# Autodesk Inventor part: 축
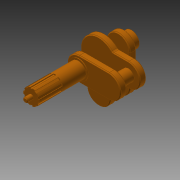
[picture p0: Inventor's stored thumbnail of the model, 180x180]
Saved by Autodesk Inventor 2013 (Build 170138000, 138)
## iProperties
Created: 2017-05
Part Number: 축
Material: 강철, 연강
Document SubType Name: Modeling
Designer: mduedu
Density: 7.86 g/cm^3
Mass: 656.198 g
Surface Area: 242.498 cm^2
Volume: 83.4857 cm^3
Author: mduedu
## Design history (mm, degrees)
sketch "스케치1"
  geometry: L1 (-38, 15)-(-17.436, 15); L2 (-38, -15)-(-17.436, -15); L3 (-15, -38)-(-15, -17.436); L4 (15, -38)-(15, -17.436); A1 r 23 centre (0, 0) between (-17.436, 15) and (-17.436, -15); A2 r 15 centre (-38, 0) between (-38, 15) and (-38, -15); A3 r 15 centre (0, -38) between (-15, -38) and (15, -38); 1 further point
  constraints: 8 end point, 8 point on circle, 4 tangent, 3 centre point, 2 horizontal, 2 vertical, 1 coincident, 1 horizontal alignment, 1 vertical alignment
  dimensions: "d0" = 46 diameter of A1; "d1" = 30 diameter of A2; "d2" = 30 diameter of A3 (= d1); "d3" = 38 distance of point (0, 0) A2.centre; "d4" = 38 distance of A3.centre point (0, 0)
extrude "돌출1" new body sketch "스케치1" distance "d5" = 8; taper "d6" = 0 deg
fillet "모깎기1" dims "d7" = 3
sketch "스케치2"
  geometry: C1 r 7.5 at (0, -38); A1 r 15 centre (0, -38) between (-15, -38) and (15, -38) reference; 1 further point
  constraints: 1 centre point, 1 coincident
  dimensions: "d8" = 15 diameter of C1
extrude "돌출2" join sketch "스케치2" distance "d9" = 17; taper "d10" = 0 deg
sketch "스케치3"
  geometry: L1 (-15, 0)-(-15, 38); L2 (15, 0)-(15, 38); C1 r 7.5 at (0, 0) reference; A1 r 15 centre (0, 0) between (-15, 0) and (15, 0); A2 r 15 centre (0, 38) between (-15, 38) and (15, 38); 1 further point
  constraints: 4 end point, 4 point on circle, 4 tangent, 2 centre point, 2 coincident
  dimensions: "d11" = 30 diameter of A1; "d12" = 30 diameter of A2 (= d11)
extrude "돌출3" join sketch "스케치3" distance "d13" = 8; taper "d14" = 0 deg
sketch "스케치4"
  geometry: C1 r 12 at (0, 38); A1 r 15 centre (0, 38) between (15, 38) and (-15, 38) reference; 1 further point
  constraints: 1 centre point, 1 coincident
  dimensions: "d15" = 24 diameter of C1
extrude "돌출4" join sketch "스케치4" distance "d16" = 1; taper "d17" = 0 deg
sketch "스케치5"
  geometry: C1 r 10 at (0, 0); 1 further point
  constraints: 1 centre point, 1 coincident
  dimensions: "d18" = 20 diameter of C1
extrude "돌출5" join sketch "스케치5" distance "d19" = 8; taper "d20" = 0 deg
sketch "스케치6"
  geometry: C1 r 7.5 at (38, 0); A1 r 15 centre (38, 0) between (38, -15) and (38, 15) reference; 1 further point
  constraints: 1 centre point, 1 coincident
  dimensions: "d21" = 15 diameter of C1
extrude "돌출6" join sketch "스케치6" distance "d22" = 17; taper "d23" = 0 deg
sketch "스케치7"
  geometry: L1 (-38, 15)-(0, 15); L2 (-38, -15)-(0, -15); C1 r 7.5 at (0, 0) reference; A1 r 15 centre (0, 0) between (0, 15) and (0, -15); A2 r 15 centre (-38, 0) between (-38, 15) and (-38, -15); 1 further point
  constraints: 4 end point, 4 point on circle, 4 tangent, 2 centre point, 2 coincident
  dimensions: "d24" = 30 diameter of A1; "d25" = 30 diameter of A2 (= d24)
extrude "돌출7" join sketch "스케치7" distance "d26" = 8; taper "d27" = 0 deg
sketch "스케치8"
  geometry: C1 r 12 at (-38, 0); 1 further point
  constraints: 1 centre point, 1 coincident
  dimensions: "d28" = 24 diameter of C1
extrude "돌출8" join sketch "스케치8" distance "d29" = 1; taper "d30" = 0 deg
sketch "스케치9"
  geometry: C1 r 10 at (0, 0); 1 further point
  constraints: 1 centre point, 1 coincident
  dimensions: "d31" = 20 diameter of C1
extrude "돌출9" join sketch "스케치9" distance "d32" = 30; taper "d33" = 0 deg
sketch "스케치10"
  geometry: L1 (1.5, 9.887)-(1.5, 8.887); L2 (1.5, 8.887)-(-1.5, 8.887); L3 (-1.5, 8.887)-(-1.5, 9.887); L4 (-4.598, 8.88)-(-4.01, 8.071); L5 (-4.01, 8.071)-(-6.437, 6.308); L6 (-6.437, 6.308)-(-7.025, 7.117); L7 (-8.939, 4.482)-(-7.988, 4.173); L8 (-7.988, 4.173)-(-8.915, 1.32); L9 (-8.915, 1.32)-(-9.866, 1.629); L10 (-9.866, -1.629)-(-8.915, -1.32); L11 (-8.915, -1.32)-(-7.988, -4.173); L12 (-7.988, -4.173)-(-8.939, -4.482); L13 (-7.025, -7.117)-(-6.437, -6.308); L14 (-6.437, -6.308)-(-4.01, -8.071); L15 (-4.01, -8.071)-(-4.598, -8.88); L16 (-1.5, -9.887)-(-1.5, -8.887); L17 (-1.5, -8.887)-(1.5, -8.887); L18 (1.5, -8.887)-(1.5, -9.887); L19 (4.598, -8.88)-(4.01, -8.071); L20 (4.01, -8.071)-(6.437, -6.308); L21 (6.437, -6.308)-(7.025, -7.117); L22 (8.939, -4.482)-(7.988, -4.173); L23 (7.988, -4.173)-(8.915, -1.32); L24 (8.915, -1.32)-(9.866, -1.629); L25 (9.866, 1.629)-(8.915, 1.32); L26 (8.915, 1.32)-(7.988, 4.173); L27 (7.988, 4.173)-(8.939, 4.482); L28 (7.025, 7.117)-(6.437, 6.308); L29 (6.437, 6.308)-(4.01, 8.071); L30 (4.01, 8.071)-(4.598, 8.88); A1 r 10 centre (0, 0) between (1.5, 9.887) and (-1.5, 9.887); A2 r 10 centre (0, 0) between (-4.598, 8.88) and (-7.025, 7.117); A3 r 10 centre (0, 0) between (-8.939, 4.482) and (-9.866, 1.629); A4 r 10 centre (0, 0) between (-9.866, -1.629) and (-8.939, -4.482); A5 r 10 centre (0, 0) between (-7.025, -7.117) and (-4.598, -8.88); A6 r 10 centre (0, 0) between (-1.5, -9.887) and (1.5, -9.887); A7 r 10 centre (0, 0) between (4.598, -8.88) and (7.025, -7.117); A8 r 10 centre (0, 0) between (8.939, -4.482) and (9.866, -1.629); A9 r 10 centre (0, 0) between (9.866, 1.629) and (8.939, 4.482); A10 r 10 centre (0, 0) between (7.025, 7.117) and (4.598, 8.88); 13 further points
  constraints: 60 end point, 20 point on circle, 10 centre point, 3 coincident, 1 horizontal, 1 midpoint, 1 parallel, 1 vertical, 1 vertical alignment, 103 other
  dimensions: "d37" = 3 distance of L1.end L2.end; "d39" = 1 distance of L2.end L3.end; "d42" = 360 deg dimension on A1.centre L1.start (derived)
extrude "돌출10" join sketch "스케치10" distance "d44" = 30; taper "d45" = 0 deg
sketch "스케치11"
  geometry: C1 r 3 at (0, 0); 1 further point
  constraints: 1 centre point, 1 coincident
  dimensions: "d49" = 6 diameter of C1
extrude "돌출11" join sketch "스케치11" distance "d50" = 8; taper "d51" = 0 deg
chamfer "모따기1" distance "d46" = 1; stored, may be unused: second distance "d47" = 2, angle "d48" = 45 deg
node "솔리드1"
node "투영된 루프1"
node "투영된 루프2"
node "투영된 루프3"
